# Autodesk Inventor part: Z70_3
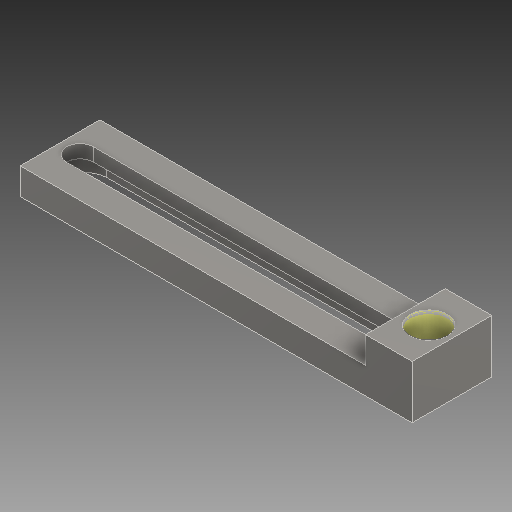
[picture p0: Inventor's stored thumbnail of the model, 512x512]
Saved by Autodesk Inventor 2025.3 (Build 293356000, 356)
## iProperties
Created: 2025-03
Part Number: Z70_3
Material: Všeobecné
Document SubType Name: Modeling
Designer: Patrik
Density: 1 g/cm^3
Appearance: Výchozí
Mass: 256.957 g
Surface Area: 566.192 cm^2
Volume: 256.957 cm^3
Author: Patrik
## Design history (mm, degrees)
feature "Base1"
node "Těleso1"
